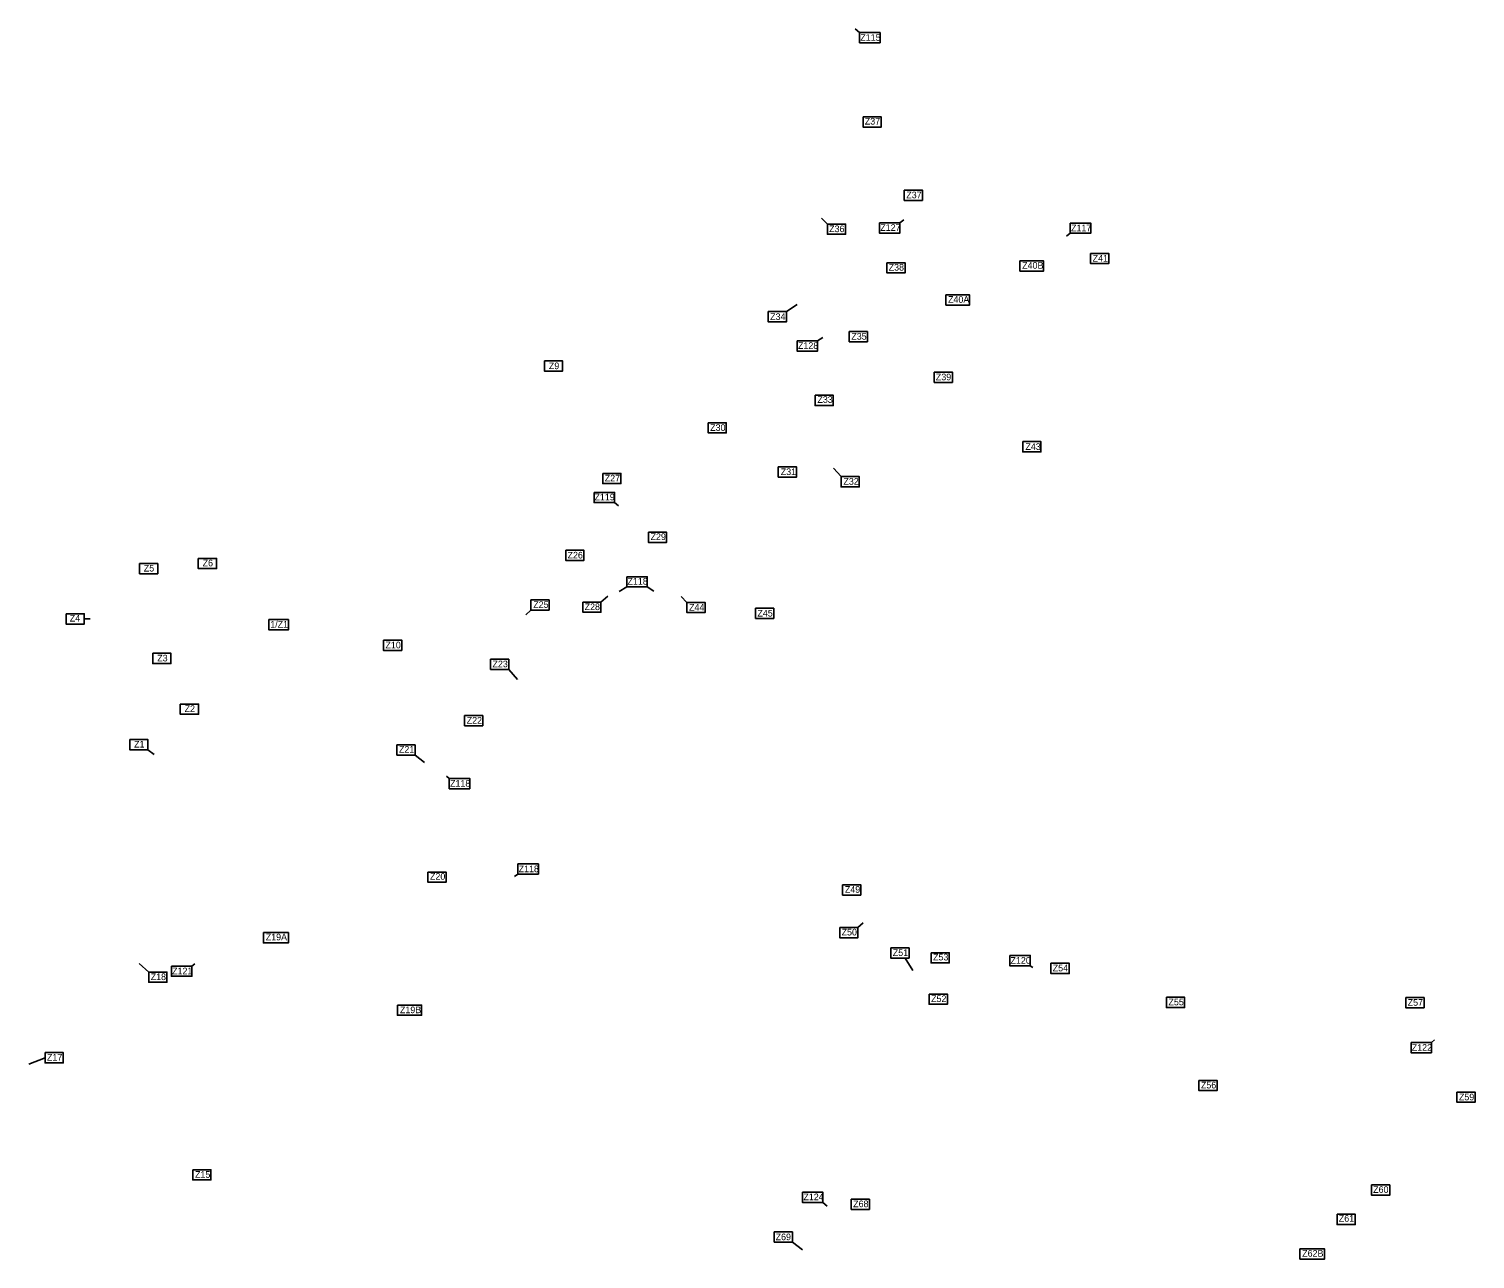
# Model space of a CAD drawing. Extents: x -443483 to -430840, y -1135277 to -1129797.
# Drawn here: x -443031 to -440855, y -1131648 to -1129797 of the extents above; entities that cross this region are included whole.
import ezdxf

# ---------------------------------------------------------------- set-up
doc = ezdxf.new("R2010")
doc.units = 0
doc.layers.add('Vrstva 3', color=7, linetype='Continuous')
doc.layers.add('Vrstva 8', color=7, linetype='Continuous')

msp = doc.modelspace()

# ---------------------------------------------------------------- linework, layer by layer
at = {"layer": 'Vrstva 3'}
for p, q in [((-441780.6, -1129802.1), (-441787.2, -1129796.7)), ((-441829.1, -1130090.3), (-441838, -1130081.7)), ((-441808.5, -1130470.4), (-441819.7, -1130457.7)), ((-442169.8, -1130659.1), (-442159.4, -1130650.4)), ((-442040.6, -1130659.7), (-442049.4, -1130650.9)), ((-442275.3, -1130671.3), (-442283.1, -1130678.3)), ((-442947.3, -1130684.5), (-442938.5, -1130684.6)), ((-442308.6, -1130760.6), (-442295.6, -1130775.5)), ((-442851.5, -1130881.4), (-442842.3, -1130888.4)), ((-442449.5, -1130889.5), (-442435.6, -1130900.4)), ((-441783.2, -1131148.9), (-441775.1, -1131141.9)), ((-441711.9, -1131195), (-441700.6, -1131213.6)), ((-442850.2, -1131215.9), (-442864.6, -1131203.1)), ((-443006.2, -1131344.9), (-443030.6, -1131354.8)), ((-441881.8, -1131622.4), (-441866.7, -1131634.1))]:
    msp.add_line(p, q, dxfattribs=at)
for points in [[(-441780.6, -1129802.1), (-441749.8, -1129802.1), (-441749.8, -1129817.5), (-441780.6, -1129817.5)], [(-441775.4, -1129929), (-441748, -1129929), (-441748, -1129944.4), (-441775.4, -1129944.4)], [(-441713.5, -1130039.3), (-441686.2, -1130039.3), (-441686.2, -1130054.7), (-441713.5, -1130054.7)], [(-441829.1, -1130090.3), (-441801.8, -1130090.3), (-441801.8, -1130105.7), (-441829.1, -1130105.7)], [(-441739.6, -1130148.5), (-441712.2, -1130148.5), (-441712.2, -1130163.9), (-441739.6, -1130163.9)], [(-441539.4, -1130145.7), (-441503.8, -1130145.7), (-441503.8, -1130161.1), (-441539.4, -1130161.1)], [(-441433.1, -1130134.4), (-441405.7, -1130134.4), (-441405.7, -1130149.8), (-441433.1, -1130149.8)], [(-441650.9, -1130196.9), (-441615.3, -1130196.9), (-441615.3, -1130212.3), (-441650.9, -1130212.3)], [(-441918.2, -1130222.1), (-441890.9, -1130222.1), (-441890.9, -1130237.5), (-441918.2, -1130237.5)], [(-441796.3, -1130252.1), (-441768.9, -1130252.1), (-441768.9, -1130267.5), (-441796.3, -1130267.5)], [(-442254.8, -1130296.3), (-442227.5, -1130296.3), (-442227.5, -1130311.7), (-442254.8, -1130311.7)], [(-441668.4, -1130313.2), (-441641, -1130313.2), (-441641, -1130328.6), (-441668.4, -1130328.6)], [(-441847.6, -1130348), (-441820.2, -1130348), (-441820.2, -1130363.4), (-441847.6, -1130363.4)], [(-442008.5, -1130389.3), (-441981.2, -1130389.3), (-441981.2, -1130404.7), (-442008.5, -1130404.7)], [(-441535.3, -1130417.8), (-441507.9, -1130417.8), (-441507.9, -1130433.2), (-441535.3, -1130433.2)], [(-441903, -1130455.8), (-441875.6, -1130455.8), (-441875.6, -1130471.2), (-441903, -1130471.2)], [(-442167.1, -1130465.6), (-442139.8, -1130465.6), (-442139.8, -1130481), (-442167.1, -1130481)], [(-441808.5, -1130470.4), (-441781.1, -1130470.4), (-441781.1, -1130485.8), (-441808.5, -1130485.8)], [(-442098.4, -1130554.1), (-442071.1, -1130554.1), (-442071.1, -1130569.5), (-442098.4, -1130569.5)], [(-442222.8, -1130581.2), (-442195.5, -1130581.2), (-442195.5, -1130596.5), (-442222.8, -1130596.5)], [(-442864.1, -1130601.3), (-442836.8, -1130601.3), (-442836.8, -1130616.7), (-442864.1, -1130616.7)], [(-442775.7, -1130593.4), (-442748.3, -1130593.4), (-442748.3, -1130608.8), (-442775.7, -1130608.8)], [(-442974.7, -1130676.8), (-442947.3, -1130676.8), (-442947.3, -1130692.2), (-442974.7, -1130692.2)], [(-442275.3, -1130655.9), (-442247.9, -1130655.9), (-442247.9, -1130671.3), (-442275.3, -1130671.3)], [(-442197.1, -1130659.1), (-442169.8, -1130659.1), (-442169.8, -1130674.5), (-442197.1, -1130674.5)], [(-442040.6, -1130659.7), (-442013.2, -1130659.7), (-442013.2, -1130675.1), (-442040.6, -1130675.1)], [(-441937.3, -1130668.5), (-441909.9, -1130668.5), (-441909.9, -1130683.9), (-441937.3, -1130683.9)], [(-442669.4, -1130685.6), (-442640.1, -1130685.6), (-442640.1, -1130701), (-442669.4, -1130701)], [(-442497.1, -1130716.5), (-442469.7, -1130716.5), (-442469.7, -1130731.9), (-442497.1, -1130731.9)], [(-442844.2, -1130736.3), (-442816.9, -1130736.3), (-442816.9, -1130751.7), (-442844.2, -1130751.7)], [(-442335.9, -1130745.2), (-442308.6, -1130745.2), (-442308.6, -1130760.6), (-442335.9, -1130760.6)], [(-442802.8, -1130812.7), (-442775.4, -1130812.7), (-442775.4, -1130828.1), (-442802.8, -1130828.1)], [(-442375, -1130829.9), (-442347.6, -1130829.9), (-442347.6, -1130845.3), (-442375, -1130845.3)], [(-442878.9, -1130866.1), (-442851.5, -1130866.1), (-442851.5, -1130881.4), (-442878.9, -1130881.4)], [(-442476.9, -1130874.1), (-442449.5, -1130874.1), (-442449.5, -1130889.5), (-442476.9, -1130889.5)], [(-442430.2, -1131065.5), (-442402.9, -1131065.5), (-442402.9, -1131080.9), (-442430.2, -1131080.9)], [(-441806.3, -1131084.7), (-441778.9, -1131084.7), (-441778.9, -1131100.1), (-441806.3, -1131100.1)], [(-441810.6, -1131148.9), (-441783.2, -1131148.9), (-441783.2, -1131164.3), (-441810.6, -1131164.3)], [(-442677.8, -1131156.7), (-442640.2, -1131156.7), (-442640.2, -1131172.1), (-442677.8, -1131172.1)], [(-441733.7, -1131179.6), (-441706.3, -1131179.6), (-441706.3, -1131195), (-441733.7, -1131195)], [(-441673.2, -1131186.9), (-441645.8, -1131186.9), (-441645.8, -1131202.2), (-441673.2, -1131202.2)], [(-442850.2, -1131215.9), (-442822.9, -1131215.9), (-442822.9, -1131231.3), (-442850.2, -1131231.3)], [(-441492.7, -1131202.8), (-441465.3, -1131202.8), (-441465.3, -1131218.2), (-441492.7, -1131218.2)], [(-441676, -1131249.1), (-441648.6, -1131249.1), (-441648.6, -1131264.5), (-441676, -1131264.5)], [(-441319, -1131254), (-441291.6, -1131254), (-441291.6, -1131269.4), (-441319, -1131269.4)], [(-440958.8, -1131254.3), (-440931.4, -1131254.3), (-440931.4, -1131269.7), (-440958.8, -1131269.7)], [(-442476, -1131265.7), (-442439.7, -1131265.7), (-442439.7, -1131281.1), (-442476, -1131281.1)], [(-443006.2, -1131337.2), (-442978.8, -1131337.2), (-442978.8, -1131352.6), (-443006.2, -1131352.6)], [(-441270.2, -1131379), (-441242.8, -1131379), (-441242.8, -1131394.4), (-441270.2, -1131394.4)], [(-440882, -1131396.5), (-440854.6, -1131396.5), (-440854.6, -1131411.9), (-440882, -1131411.9)], [(-442784.1, -1131513.4), (-442756.7, -1131513.4), (-442756.7, -1131528.8), (-442784.1, -1131528.8)], [(-441010.2, -1131536.4), (-440982.9, -1131536.4), (-440982.9, -1131551.8), (-441010.2, -1131551.8)], [(-441793.2, -1131557.8), (-441765.8, -1131557.8), (-441765.8, -1131573.2), (-441793.2, -1131573.2)], [(-441062.3, -1131580.5), (-441035, -1131580.5), (-441035, -1131595.9), (-441062.3, -1131595.9)], [(-441909.1, -1131607), (-441881.8, -1131607), (-441881.8, -1131622.4), (-441909.1, -1131622.4)], [(-441118.1, -1131632.5), (-441081, -1131632.5), (-441081, -1131647.9), (-441118.1, -1131647.9)]]:
    msp.add_lwpolyline(points, close=True, dxfattribs=at)
at = {"layer": 'Vrstva 8'}
for p, q in [((-441720.1, -1130088.6), (-441714.3, -1130084)), ((-441463.6, -1130104.2), (-441469.4, -1130108.5)), ((-441890.9, -1130222.1), (-441874.8, -1130211.2)), ((-441844, -1130266.2), (-441836.1, -1130260.9)), ((-442149.3, -1130509.6), (-442143.6, -1130514.2)), ((-442131, -1130636.5), (-442142.2, -1130643.1)), ((-442100.3, -1130636.5), (-442090.5, -1130642.7)), ((-442398, -1130924.7), (-442402.3, -1130921.1)), ((-442294.8, -1131068.6), (-442299.8, -1131072.4)), ((-442785.3, -1131206.9), (-442780.8, -1131203.4)), ((-441523.9, -1131206.4), (-441520.2, -1131209.2)), ((-440920.2, -1131322), (-440915.5, -1131317.9)), ((-441835.8, -1131562.7), (-441829.5, -1131568.4))]:
    msp.add_line(p, q, dxfattribs=at)
for points in [[(-441750.9, -1130088.6), (-441720.1, -1130088.6), (-441720.1, -1130104), (-441750.9, -1130104)], [(-441463.6, -1130088.8), (-441432.8, -1130088.8), (-441432.8, -1130104.2), (-441463.6, -1130104.2)], [(-441463.6, -1130088.8), (-441432.8, -1130088.8), (-441432.8, -1130104.2), (-441463.6, -1130104.2)], [(-441874.8, -1130266.2), (-441844, -1130266.2), (-441844, -1130281.6), (-441874.8, -1130281.6)], [(-442180.1, -1130494.2), (-442149.3, -1130494.2), (-442149.3, -1130509.6), (-442180.1, -1130509.6)], [(-442131, -1130621.1), (-442100.3, -1130621.1), (-442100.3, -1130636.5), (-442131, -1130636.5)], [(-442398, -1130924.7), (-442367.2, -1130924.7), (-442367.2, -1130940.1), (-442398, -1130940.1)], [(-442294.8, -1131053.2), (-442264, -1131053.2), (-442264, -1131068.6), (-442294.8, -1131068.6)], [(-441554.7, -1131191), (-441523.9, -1131191), (-441523.9, -1131206.4), (-441554.7, -1131206.4)], [(-442816.1, -1131206.9), (-442785.3, -1131206.9), (-442785.3, -1131222.3), (-442816.1, -1131222.3)], [(-440951, -1131322), (-440920.2, -1131322), (-440920.2, -1131337.4), (-440951, -1131337.4)], [(-441866.6, -1131547.3), (-441835.8, -1131547.3), (-441835.8, -1131562.7), (-441866.6, -1131562.7)]]:
    msp.add_lwpolyline(points, close=True, dxfattribs=at)

# ---------------------------------------------------------------- texts
at = {"layer": 'Vrstva 3'}
for s, p in [('Z115', (-441779.6, -1129814.6)), ('Z37', (-441772.8, -1129940.6)), ('Z37', (-441710.4, -1130051.5)), ('Z36', (-441826.5, -1130102.5)), ('Z38', (-441736.9, -1130160.4)), ('Z40B', (-441536, -1130157.5)), ('Z41', (-441430, -1130146.8)), ('Z40A', (-441647.6, -1130208.8)), ('Z34', (-441915.3, -1130234.7)), ('Z35', (-441793.1, -1130264.3)), ('Z9', (-442248.2, -1130308.7)), ('Z39', (-441665.9, -1130325.4)), ('Z33', (-441844.1, -1130359.4)), ('Z30', (-442005.5, -1130401.6)), ('Z43', (-441531.1, -1130430.2)), ('Z31', (-441899.3, -1130468.1)), ('Z27', (-442164.1, -1130477.7)), ('Z32', (-441805, -1130482.6)), ('Z29', (-442095.2, -1130565.8)), ('Z26', (-442220.1, -1130593.6)), ('Z5', (-442857.7, -1130613.2)), ('Z6', (-442769.2, -1130605.4)), ('Z25', (-442271.7, -1130668)), ('Z28', (-442194.4, -1130671.3)), ('Z44', (-442037.3, -1130672.2)), ('Z45', (-441934.4, -1130681)), ('Z4', (-442969.1, -1130688.5)), ('1/Z1', (-442667.4, -1130697.6)), ('Z10', (-442494.1, -1130728.9)), ('Z3', (-442837.5, -1130748.5)), ('Z23', (-442333, -1130757.3)), ('Z2', (-442796.3, -1130824.6)), ('Z22', (-442371.8, -1130842.1)), ('Z1', (-442872.3, -1130878.1)), ('Z21', (-442473.8, -1130885.9)), ('Z20', (-442427.1, -1131077)), ('Z49', (-441802.8, -1131096.7)), ('Z50', (-441807.7, -1131160.9)), ('Z19A', (-442674.2, -1131168.3)), ('Z51', (-441730.7, -1131191.7)), ('Z53', (-441670.1, -1131198.5)), ('Z18', (-442847.3, -1131228.1)), ('Z54', (-441490.1, -1131214.9)), ('Z52', (-441673.1, -1131261.1)), ('Z55', (-441315.9, -1131266)), ('Z57', (-440956, -1131266.7)), ('Z19B', (-442472.3, -1131277.9)), ('Z17', (-443003.4, -1131349.3)), ('Z56', (-441267.1, -1131391.1)), ('Z59', (-440878.9, -1131409)), ('Z15', (-442780.6, -1131525.6)), ('Z60', (-441007.9, -1131548.3)), ('Z68', (-441790.3, -1131569.8)), ('Z61', (-441059.6, -1131591.7)), ('Z69', (-441907, -1131619.5)), ('Z62B', (-441114.7, -1131644.3))]:
    msp.add_text(s, height=10, dxfattribs=at).set_placement(p)
at = {"layer": 'Vrstva 8'}
for s, p in [('Z127', (-441749.5, -1130100.6)), ('Z117', (-441462.5, -1130101.2)), ('Z128', (-441873.4, -1130278.2)), ('Z119', (-442179.6, -1130506.2)), ('Z118', (-442129.9, -1130632.9)), ('Z118', (-442396.9, -1130937.1)), ('Z118', (-442293.7, -1131065.7)), ('Z120', (-441553.6, -1131203.5)), ('Z121', (-442815.1, -1131219.3)), ('Z122', (-440949.9, -1131334.5)), ('Z124', (-441865.2, -1131559.3))]:
    msp.add_text(s, height=10, dxfattribs=at).set_placement(p)

doc.saveas('drawing.dxf')
